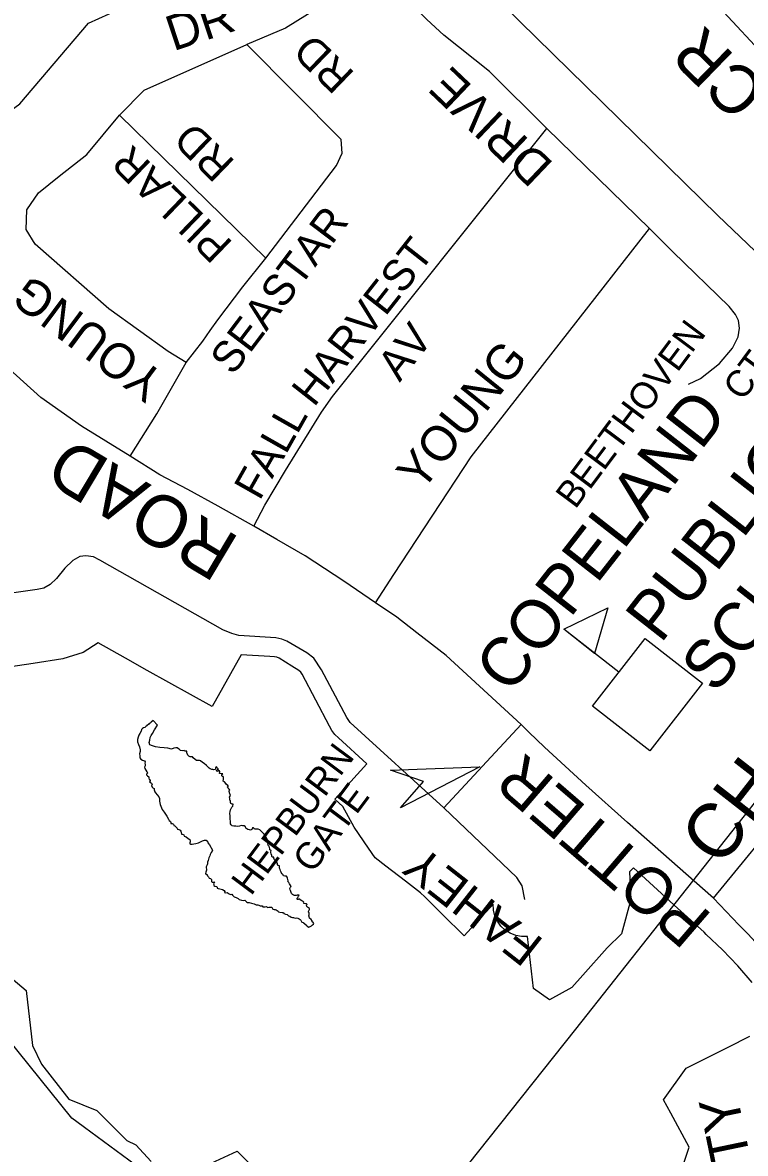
# Model space of a CAD drawing. Extents: x 586326 to 623965, y 4819854 to 4857850.
# Drawn here: x 599494 to 599867, y 4833487 to 4834070 of the extents above; entities that cross this region are included whole.
import ezdxf

# ---------------------------------------------------------------- set-up
doc = ezdxf.new("R2010")
doc.units = 0
for name, color, linetype in [('Hydro ROW', 7, 'Continuous'), ('Lots_Concessions', 7, 'Continuous'), ('Major Rds and Hwys', 7, 'Continuous'), ('Major Rds Lbls', 7, 'Continuous'), ('Minor Rd Lbls', 7, 'Continuous'), ('Minor Rds', 7, 'Continuous'), ('Park Outlines', 7, 'Continuous'), ('Proposed Secondary Rds', 7, 'Continuous'), ('School Syms_Lbls', 7, 'Continuous'), ('Secondary Rds Lbls', 7, 'Continuous'), ('SWM Ponds', 7, 'Continuous')]:
    doc.layers.add(name, color=color, linetype=linetype)

msp = doc.modelspace()

# ---------------------------------------------------------------- linework, layer by layer
at = {"layer": 'Hydro ROW'}
for p, q in [((599519.76, 4833504.76), (599376.71, 4833681.65)), ((599616.47, 4833433.79), (599519.76, 4833504.76))]:
    msp.add_line(p, q, dxfattribs=at)
at = {"layer": 'Lots_Concessions'}
for p, q in [((599779.82, 4833550.59), (599907.03, 4833711.59)), ((599701.81, 4833452.63), (599779.82, 4833550.59))]:
    msp.add_line(p, q, dxfattribs=at)
at = {"layer": 'Major Rds and Hwys'}
for points in [[(599853.16, 4833970.31), (599640.11, 4834179.09), (599625.32, 4834193.52)], [(600011.04, 4833819.79), (599853.16, 4833970.31)], [(599549.78, 4833846.2), (599524.65, 4833861.65), (599503.75, 4833876.57), (599485.78, 4833892.65), (599456.57, 4833921.05), (599440.34, 4833938.09)], [(599613.73, 4833810.19), (599595.23, 4833820.45), (599579.57, 4833828.97), (599565.15, 4833836.63), (599549.78, 4833846.2)], [(599676.54, 4833770.64), (599660.16, 4833781.82), (599640.14, 4833794.89), (599625.54, 4833803.28), (599613.73, 4833810.19)], [(599751.61, 4833707.8), (599712.93, 4833743.44), (599697.9, 4833755.12), (599687.5, 4833763.24), (599676.54, 4833770.64)], [(599850.89, 4833618.2), (599806.53, 4833657.23), (599785.04, 4833676.54), (599763.76, 4833696.09), (599755.61, 4833703.84), (599751.61, 4833707.8)], [(599917.3, 4833528.69), (599905.45, 4833552.08), (599897.62, 4833564.59), (599889.01, 4833577.45), (599882.52, 4833585.19), (599874.61, 4833593.5), (599868.63, 4833599.75), (599864.04, 4833604.44), (599850.89, 4833618.2)]]:
    msp.add_lwpolyline(points, dxfattribs=at)
at = {"layer": 'Minor Rd Lbls'}
for p, q in [((599684.25, 4833684.24), (599730.32, 4833685.92)), ((599730.32, 4833685.92), (599689.3, 4833664.89)), ((599701.29, 4833678.35), (599684.25, 4833684.24)), ((599689.3, 4833664.89), (599701.29, 4833678.35)), ((599701.29, 4833678.35), (599701.29, 4833678.35))]:
    msp.add_line(p, q, dxfattribs=at)
msp.add_lwpolyline([(599701.29, 4833678.35), (599684.25, 4833684.24), (599730.32, 4833685.92), (599689.3, 4833664.89)], close=True, dxfattribs=at)
at = {"layer": 'Minor Rds'}
for points in [[(600063.7, 4833991.31), (600016.02, 4833933.5), (600008.18, 4833930.72), (600001.43, 4833931.74), (599872.33, 4834058.03), (599779.99, 4834157.32), (599774.65, 4834167.73), (599778.38, 4834177.34), (599819.22, 4834217.1), (599838.97, 4834225.91), (599849.01, 4834228.09), (599876.87, 4834228.31)], [(599764.98, 4834015.28), (599735.33, 4834044.61), (599711.8, 4834063.4), (599702.97, 4834071.54), (599683.31, 4834091.25), (599674.93, 4834093.98), (599667.98, 4834093.53), (599646.42, 4834077.06), (599629.95, 4834066.99), (599610.04, 4834058.64)], [(599544.4, 4834022.09), (599557.14, 4834034.97), (599610.04, 4834058.64)], [(599619.86, 4833948.34), (599656.42, 4833996.18), (599659.33, 4834002.54), (599658.69, 4834009.61), (599610.04, 4834058.64)], [(599578.8, 4833894.53), (599569.4, 4833900.18), (599538.79, 4833922.18), (599500.88, 4833955.62), (599496.21, 4833963.1), (599496.56, 4833973.34), (599502.46, 4833982.11), (599513.12, 4833990.72), (599527.41, 4834001.81), (599544.4, 4834022.09)], [(599619.86, 4833948.34), (599544.4, 4834022.09)], [(599613.73, 4833810.19), (599619.37, 4833820.99), (599629.97, 4833838.79), (599648.63, 4833868.98), (599654.33, 4833877.06), (599764.98, 4834015.28)], [(599817.9, 4833963.67), (599764.98, 4834015.28)], [(599676.54, 4833770.64), (599686.01, 4833785.17), (599725.78, 4833845.86), (599817.9, 4833963.67)], [(599829.99, 4833951.55), (599817.9, 4833963.67)], [(599578.8, 4833894.53), (599587.32, 4833905.63), (599591.16, 4833911.08), (599595.08, 4833916.47), (599607.95, 4833933.53), (599619.86, 4833948.34)], [(599838.1, 4833883.32), (599844.23, 4833886.24), (599854.12, 4833893.95), (599860.77, 4833901.9), (599863.69, 4833907.77), (599864.43, 4833912.2), (599863.88, 4833916.21), (599862.31, 4833919.37), (599859.05, 4833923.5), (599829.99, 4833951.55)], [(599549.78, 4833846.2), (599563.53, 4833868.02), (599578.8, 4833894.53)], [(599523.92, 4833794.47), (599520.29, 4833792.38), (599516.2, 4833788.49), (599511.83, 4833783.18), (599508.61, 4833780.11), (599505.27, 4833778.07), (599501.76, 4833777.45), (599467.93, 4833772.56), (599463.77, 4833772.13), (599460.81, 4833772.35), (599458.15, 4833773.27), (599455.38, 4833775.08), (599446.32, 4833789.37), (599427.36, 4833816.37)], [(599711.79, 4833664.86), (599663.43, 4833708.92), (599661.61, 4833711.5), (599648.58, 4833736.04), (599644.62, 4833741.99), (599641.07, 4833744.78), (599630.74, 4833750.86), (599628.19, 4833751.91), (599625.1, 4833752.47), (599605.9, 4833753.75), (599602.33, 4833754.68), (599597.76, 4833756.63), (599534.17, 4833792.59), (599530.83, 4833794.26), (599526.97, 4833794.84), (599523.92, 4833794.47)], [(599711.79, 4833664.86), (599751.61, 4833707.8)], [(599753.56, 4833617.57), (599752.17, 4833624.59), (599749.43, 4833628.82), (599711.79, 4833664.86)]]:
    msp.add_lwpolyline(points, dxfattribs=at)
at = {"layer": 'Park Outlines'}
msp.add_lwpolyline([(599623.52, 4834168.61), (599454.66, 4834061.42), (599443.22, 4834053.82), (599432.11, 4834045.77), (599421.33, 4834037.28), (599410.9, 4834028.36), (599400.84, 4834019.02), (599400.84, 4834019.02), (599401.01, 4834018.77), (599418.91, 4833993.11), (599422.94, 4833987.34), (599424.92, 4833989.2), (599456.28, 4834001.33), (599492.83, 4834027.93), (599528.31, 4834069.63), (599597.74, 4834100.97), (599616.92, 4834107.86), (599629.18, 4834119.39), (599654.99, 4834137.73), (599623.52, 4834168.61)], close=True, dxfattribs=at)
for points in [[(599870.95, 4833574.72), (599863.43, 4833583.37), (599855.52, 4833591.65), (599847.23, 4833599.57), (599846.05, 4833600.64), (599830.73, 4833614.61), (599830.5, 4833614.81), (599824.15, 4833620.63), (599809.59, 4833633.96), (599807.57, 4833631.75), (599808.33, 4833617.53), (599803.43, 4833599.89), (599796.1, 4833592.55), (599783.43, 4833578.46), (599777.82, 4833572.22), (599766.37, 4833565.79), (599757.97, 4833571.68), (599754.93, 4833598.51), (599751.88, 4833598.47), (599748.87, 4833599.02), (599746.02, 4833600.13), (599743.44, 4833601.76), (599741.21, 4833603.85), (599739.42, 4833606.33), (599738.14, 4833609.1), (599737.4, 4833612.06), (599737.24, 4833615.12), (599722.27, 4833598.76), (599711.01, 4833609.86), (599701.89, 4833618.84), (599699.78, 4833620.91), (599691.95, 4833626.94), (599681.77, 4833634.78), (599676.24, 4833639.03), (599672.84, 4833643.99), (599665.41, 4833654.81), (599659.56, 4833665.57), (599655.42, 4833669.35), (599671.99, 4833687.44), (599657.33, 4833700.87), (599655.55, 4833702.69), (599654, 4833704.71), (599652.69, 4833706.89), (599638.63, 4833733.77), (599637.86, 4833734.85), (599636.83, 4833735.7), (599633.34, 4833737.86), (599626.71, 4833741.97), (599625.59, 4833742.49), (599624.39, 4833742.71), (599621.89, 4833742.87), (599607.13, 4833743.81), (599592.23, 4833717.07), (599581.05, 4833723.3), (599569.87, 4833729.52), (599558.69, 4833735.75), (599547.51, 4833741.97), (599533.26, 4833749.91), (599525.6, 4833744.97), (599515.09, 4833741.62), (599499.72, 4833739.32), (599487.07, 4833737.43)], [(599445.1, 4833613.62), (599496.12, 4833570.54), (599499.42, 4833542.27), (599504.06, 4833532.65), (599518.22, 4833514.57), (599532.63, 4833508.78), (599548.05, 4833493.23), (599552.7, 4833491.03), (599560.63, 4833482.42)], [(599870.9, 4833380.77), (599856.78, 4833389.8), (599856.08, 4833400.25), (599855.59, 4833407.74), (599840.99, 4833411.77), (599832.79, 4833414.03), (599833.59, 4833422.5), (599834.81, 4833435.37), (599835.43, 4833441.8), (599831.69, 4833447.16), (599826.41, 4833454.72), (599827.78, 4833458.73), (599832.48, 4833472.47), (599837.17, 4833486.2), (599838.38, 4833489.74), (599828.87, 4833507.35), (599825.19, 4833514.16), (599836.81, 4833530.57), (599858.46, 4833541.35), (599869.74, 4833546.97)], [(599584.86, 4833478.44), (599605.14, 4833487.74), (599630.57, 4833461.99)]]:
    msp.add_lwpolyline(points, dxfattribs=at)
at = {"layer": 'Proposed Secondary Rds'}
msp.add_lwpolyline([(599850.89, 4833618.2), (599890.96, 4833667.06), (599934.82, 4833723.2), (599981.58, 4833783.54), (600011.04, 4833819.79)], dxfattribs=at)
at = {"layer": 'School Syms_Lbls'}
msp.add_line((599802.04, 4833734.77), (599773.63, 4833756.96), dxfattribs=at)
for points in [[(599773.63, 4833756.96), (599796.41, 4833768), (599789.5, 4833744.49)], [(599788.41, 4833717.32), (599815.67, 4833752.22), (599845.28, 4833729.09), (599818.01, 4833694.19)]]:
    msp.add_lwpolyline(points, close=True, dxfattribs=at)
at = {"layer": 'SWM Ponds'}
msp.add_lwpolyline([(599554.2, 4833697.53), (599554.7, 4833696.26), (599554.98, 4833694.71), (599554.94, 4833693.81), (599554.74, 4833692.64), (599554.85, 4833691.73), (599554.88, 4833690.58), (599555.34, 4833689.92), (599556.23, 4833689.42), (599556.72, 4833689.19), (599557.25, 4833689.14), (599557.6, 4833688.61), (599557.42, 4833687.93), (599557.52, 4833687.13), (599557.51, 4833686.52), (599557.26, 4833685.74), (599557.49, 4833685.05), (599557.9, 4833684.32), (599558.52, 4833683.42), (599558.89, 4833682.83), (599558.23, 4833682.26), (599558.2, 4833681.88), (599558.83, 4833681.39), (599559.48, 4833680.83), (599559.53, 4833680.17), (599559.67, 4833679.5), (599560.25, 4833679.2), (599560.11, 4833678.75), (599559.85, 4833678.23), (599560.88, 4833677.58), (599561.13, 4833676.77), (599560.87, 4833676.31), (599561.22, 4833675.51), (599561.61, 4833675.16), (599562.16, 4833674.74), (599562.27, 4833674.03), (599562.54, 4833673), (599562.91, 4833672.55), (599563.78, 4833671.57), (599564.58, 4833670.48), (599565.01, 4833669.58), (599564.91, 4833668.22), (599565.26, 4833666.56), (599566.33, 4833663.98), (599567.33, 4833662.64), (599568.82, 4833660.55), (599569.59, 4833658.97), (599569.96, 4833658.32), (599570.62, 4833657.86), (599570.9, 4833657.23), (599570.87, 4833656.79), (599571.49, 4833656.67), (599572.16, 4833656.35), (599572.33, 4833655.7), (599572.93, 4833655.49), (599573.5, 4833655.04), (599574.04, 4833654.42), (599574.34, 4833653.82), (599575.03, 4833653.65), (599575.73, 4833653.3), (599575.97, 4833652.75), (599576.2, 4833651.86), (599576.27, 4833651.29), (599576.9, 4833651.31), (599577.6, 4833650.97), (599577.75, 4833650.29), (599578.79, 4833649.79), (599579.74, 4833649.04), (599580.71, 4833648.44), (599580.87, 4833647.83), (599580.76, 4833647.25), (599580.68, 4833646.82), (599580.71, 4833646.33), (599581.06, 4833646.06), (599581.78, 4833646.06), (599582.79, 4833646.3), (599583.78, 4833646.45), (599585.05, 4833646.84), (599586.1, 4833647.26), (599587.13, 4833647.79), (599588.15, 4833648.17), (599589.1, 4833648.14), (599589.8, 4833647.59), (599589.98, 4833646.84), (599590.74, 4833645.78), (599592.42, 4833642.93), (599592.22, 4833642.42), (599591.66, 4833641.83), (599591.07, 4833640.81), (599590.99, 4833640.05), (599590.51, 4833638.98), (599590.15, 4833637.73), (599589.84, 4833636.74), (599589.78, 4833636.01), (599589.59, 4833635.5), (599589.13, 4833634.32), (599589.23, 4833632.75), (599588.87, 4833631.69), (599588.79, 4833630.99), (599589.05, 4833630.48), (599589.61, 4833630.4), (599589.84, 4833629.71), (599590.28, 4833629.16), (599590.68, 4833628.49), (599591.31, 4833628.31), (599591.79, 4833627.9), (599591.83, 4833627.28), (599591.87, 4833626.79), (599592.13, 4833626.48), (599592.71, 4833626.49), (599593.45, 4833626.58), (599593.07, 4833626.1), (599592.93, 4833625.65), (599592.98, 4833625.2), (599593.05, 4833624.69), (599593.63, 4833624.39), (599594.45, 4833624.31), (599594.7, 4833623.91), (599594.82, 4833623.41), (599595.32, 4833623.27), (599596.17, 4833622.97), (599596.9, 4833622.86), (599597.56, 4833622.65), (599598.34, 4833622.2), (599598.77, 4833621.7), (599598.59, 4833621.08), (599599.15, 4833620.94), (599599.91, 4833621.07), (599600.99, 4833620.48), (599601.61, 4833620.15), (599602.28, 4833620.32), (599602.74, 4833619.82), (599603.48, 4833619), (599604.52, 4833618.49), (599605.65, 4833618.1), (599606.19, 4833617.6), (599607.35, 4833617.26), (599608.15, 4833617.09), (599608.95, 4833617.14), (599609.85, 4833616.38), (599610.39, 4833615.96), (599611.28, 4833615.98), (599612.43, 4833615.6), (599613.77, 4833615.22), (599614.91, 4833614.84), (599615.74, 4833614.86), (599616.33, 4833614.55), (599617.02, 4833614.32), (599617.59, 4833614.34), (599618.05, 4833614.33), (599618.36, 4833613.74), (599618.83, 4833613.68), (599619.48, 4833613.73), (599620.24, 4833613.85), (599620.78, 4833613.49), (599621.38, 4833613.53), (599622.04, 4833613.53), (599622.92, 4833613.58), (599623.16, 4833613.17), (599623.51, 4833612.59), (599624.22, 4833612.44), (599624.68, 4833612.44), (599625.26, 4833612.19), (599625.65, 4833611.84), (599626.23, 4833611.54), (599626.45, 4833611.22), (599627.15, 4833611.07), (599628.33, 4833610.87), (599628.91, 4833610.77), (599629.21, 4833610.29), (599630.03, 4833609.9), (599630.93, 4833609.8), (599631.6, 4833609.14), (599632.29, 4833608.92), (599632.87, 4833608.4), (599633.63, 4833608.27), (599634.15, 4833608.27), (599634.95, 4833607.85), (599635.65, 4833608.03), (599636.33, 4833607.91), (599637.15, 4833607.58), (599637.64, 4833607.29), (599637.99, 4833606.82), (599638.32, 4833606.25), (599638.51, 4833605.9), (599639.37, 4833605.75), (599639.37, 4833605.43), (599640, 4833604.99), (599641.03, 4833604.18), (599641.18, 4833603.86), (599642.05, 4833603.34), (599642.35, 4833603.46), (599642.76, 4833603.66), (599643.08, 4833603.87), (599643.4, 4833604.02), (599643.96, 4833604.41), (599644.46, 4833604.79), (599644.66, 4833605.24), (599644.37, 4833605.73), (599643.82, 4833606.06), (599643.72, 4833606.6), (599643.24, 4833607.23), (599642.4, 4833607.93), (599642.16, 4833608.54), (599642.06, 4833609.07), (599642.19, 4833609.69), (599642.19, 4833610.62), (599641.86, 4833610.92), (599641.85, 4833611.29), (599642.11, 4833611.76), (599642.39, 4833612.31), (599642.42, 4833612.95), (599641.93, 4833613.18), (599641.39, 4833613.6), (599641.03, 4833613.99), (599640.84, 4833614.6), (599641.13, 4833615.04), (599640.83, 4833615.37), (599640.28, 4833615.39), (599639.67, 4833615.46), (599639.31, 4833615.99), (599639.45, 4833616.24), (599639.13, 4833616.55), (599638.51, 4833616.88), (599637.56, 4833617.36), (599636.95, 4833617.89), (599636.63, 4833617.62), (599636.21, 4833617.54), (599635.84, 4833617.83), (599635.98, 4833618.24), (599636.44, 4833618.54), (599636.74, 4833619.22), (599637, 4833619.8), (599636.62, 4833619.84), (599636.09, 4833619.69), (599635.48, 4833619.56), (599634.73, 4833619.52), (599634.19, 4833619.69), (599633.56, 4833620.13), (599633.19, 4833620.57), (599633.03, 4833621.16), (599632.74, 4833621.64), (599632.54, 4833622.11), (599632.42, 4833622.61), (599632.34, 4833623.29), (599632.53, 4833623.86), (599632.93, 4833624.31), (599632.44, 4833625.06), (599632.13, 4833625.66), (599631.68, 4833626.32), (599631.18, 4833626.86), (599631.4, 4833627.21), (599631.29, 4833627.8), (599631.1, 4833628.47), (599630.93, 4833629.11), (599630.5, 4833629.6), (599629.63, 4833629.61), (599629.07, 4833629.69), (599628.87, 4833630.21), (599628.5, 4833630.6), (599628.09, 4833630.86), (599627.71, 4833631.68), (599627.42, 4833632.37), (599627.26, 4833633.01), (599626.99, 4833633.73), (599626.85, 4833634.46), (599626.93, 4833634.96), (599626.19, 4833635.12), (599625.96, 4833635.56), (599625.94, 4833636.19), (599625.6, 4833636.61), (599625.41, 4833637.22), (599624.83, 4833637.52), (599624.33, 4833638.06), (599624.04, 4833638.81), (599624.08, 4833639.39), (599623.25, 4833639.37), (599623.04, 4833639.69), (599622.91, 4833640.25), (599622.66, 4833641.11), (599622.49, 4833641.81), (599622.39, 4833642.15), (599622.61, 4833642.9), (599622, 4833643.22), (599621.9, 4833643.76), (599621.82, 4833644.44), (599621.67, 4833644.97), (599621.32, 4833645.19), (599621.1, 4833645.62), (599620.93, 4833646.26), (599621.34, 4833646.66), (599621.09, 4833647.12), (599620.78, 4833647.58), (599620.84, 4833647.92), (599620.54, 4833648.72), (599620.21, 4833649.34), (599619.76, 4833650.15), (599618.94, 4833651.2), (599618.3, 4833651.96), (599617.64, 4833652.68), (599616.83, 4833653.42), (599615.97, 4833653.83), (599615.3, 4833653.89), (599614.35, 4833653.86), (599613.86, 4833653.95), (599613.87, 4833654.24), (599613.44, 4833654.47), (599613.04, 4833654.48), (599612.75, 4833654.04), (599612.59, 4833653.65), (599611.94, 4833653.34), (599611.37, 4833653.53), (599610.63, 4833653.7), (599610.03, 4833653.91), (599609.63, 4833654.32), (599609.35, 4833654.95), (599608.68, 4833655.47), (599607.75, 4833655.53), (599607.22, 4833655.64), (599606.29, 4833655.44), (599605.4, 4833655.21), (599604.43, 4833655.41), (599603.39, 4833655.4), (599602.45, 4833655.51), (599601.96, 4833656), (599601.66, 4833656.6), (599601.58, 4833657.48), (599601.4, 4833659.42), (599601.43, 4833660.78), (599601.33, 4833661.83), (599601.47, 4833662.85), (599601.68, 4833663.72), (599601.93, 4833664.44), (599602.34, 4833665.09), (599602.81, 4833665.76), (599603.01, 4833666.67), (599602.46, 4833666.75), (599601.75, 4833667.1), (599601.6, 4833667.62), (599601.68, 4833668.38), (599601.37, 4833668.83), (599601.21, 4833669.62), (599601.19, 4833670.25), (599601.61, 4833671.11), (599601.54, 4833671.62), (599601.23, 4833672.02), (599601.11, 4833672.58), (599600.98, 4833673.4), (599601.31, 4833674.01), (599600.94, 4833674.4), (599600.34, 4833675.07), (599600.16, 4833675.65), (599600.62, 4833675.83), (599600.29, 4833676.39), (599599.59, 4833676.94), (599599.16, 4833677.44), (599598.49, 4833678.16), (599597.86, 4833678.63), (599597.99, 4833679.61), (599598.1, 4833680.42), (599597.89, 4833681), (599597.52, 4833680.92), (599597.21, 4833681.27), (599597.21, 4833681.83), (599597.63, 4833682.38), (599596.76, 4833682.44), (599595.89, 4833682.45), (599596.1, 4833683.37), (599596.03, 4833683.88), (599595.64, 4833683.83), (599595, 4833683.61), (599594.57, 4833683.72), (599594.4, 4833684.28), (599594.86, 4833684.54), (599595.41, 4833684.68), (599595.35, 4833684.98), (599594.76, 4833685.54), (599594.33, 4833686.03), (599594.1, 4833685.8), (599593.93, 4833685.26), (599593.75, 4833684.64), (599593.08, 4833684.44), (599592.55, 4833684.6), (599591.99, 4833684.68), (599591.06, 4833685), (599590.59, 4833685.31), (599590.15, 4833685.81), (599589.21, 4833686.64), (599588.07, 4833687.74), (599587.25, 4833688.27), (599586.23, 4833689.13), (599585.69, 4833689.29), (599585.2, 4833689.26), (599584.52, 4833689.18), (599584.02, 4833689.32), (599583.41, 4833689.79), (599582.42, 4833690.56), (599581.99, 4833691.06), (599581.44, 4833691.08), (599580.8, 4833691.11), (599580.09, 4833691.46), (599579.57, 4833691.99), (599579.26, 4833692.88), (599579.01, 4833693.28), (599579.09, 4833693.98), (599578.65, 4833694.07), (599577.9, 4833694), (599577.65, 4833694.44), (599576.66, 4833694.29), (599575.76, 4833694.34), (599575.27, 4833694.87), (599574.84, 4833695.31), (599574.03, 4833695.78), (599573.43, 4833695.74), (599572.36, 4833695.55), (599571.14, 4833695.17), (599569.35, 4833695.64), (599567.45, 4833695.69), (599565.23, 4833695.88), (599562.93, 4833696.35), (599561.85, 4833696.68), (599560.9, 4833696.91), (599559.92, 4833697.36), (599559.73, 4833698.44), (599559.92, 4833699.73), (599560.21, 4833701.14), (599560.71, 4833702.19), (599561.33, 4833703.24), (599562.44, 4833705.05), (599563.88, 4833707.41), (599561.79, 4833709.86), (599560.62, 4833709.03), (599560.14, 4833708.54), (599559.6, 4833708.24), (599559.22, 4833707.82), (599558.85, 4833707.49), (599558.48, 4833707.55), (599558.42, 4833707.06), (599558, 4833706.72), (599557.47, 4833706.31), (599556.8, 4833706.17), (599556.13, 4833705.77), (599555.65, 4833705.16), (599555.44, 4833704.3), (599554.91, 4833703.23), (599554.3, 4833702.38), (599553.94, 4833701.27), (599553.65, 4833700.11), (599553.65, 4833698.93)], close=True, dxfattribs=at)

# ---------------------------------------------------------------- texts
at = {"layer": 'Major Rds Lbls'}
for s, height, rotation, p in [('ROAD', 26.76, 149.17137, (599607.15, 4833803.78)), ('POTTER', 23.959, 139.27751, (599851, 4833609.19))]:
    msp.add_text(s, height=height, rotation=rotation, dxfattribs=at).set_placement(p)
at = {"layer": 'Minor Rd Lbls'}
for s, height, rotation, p in [('DR ', 18.086, 18.31159, (599572.11, 4834055.03)), ('CUTTERS CR', 25.002, 135.85622, (599999.82, 4833919.28)), ('RD', 16.031, 135.97944, (599666.27, 4834043.62)), ('DRIVE', 18.086, 136.40833, (599768.97, 4833997.02)), ('RD', 16.031, 135.97944, (599604.56, 4833998.06)), ('PILLAR', 16.031, 135.97944, (599603.41, 4833956.22)), ('SEASTAR', 16.031, 52.85837, (599602.84, 4833887.38)), ('HARVEST', 16.031, 51.84284, (599644.73, 4833871.09)), ('YOUNG ', 18.086, 143.20262, (599569.1, 4833887.4)), ('AV', 16.031, 51.84284, (599688.97, 4833884.03)), ('BEETHOVEN', 13.788, 53.23564, (599779.58, 4833818.45)), ('YOUNG ', 18.086, 51.06417, (599700.2, 4833827.38)), ('CT', 13.788, 53.23564, (599865.97, 4833874.09)), ('FALL', 16.031, 60.49047, (599616.68, 4833822.83)), ('HEPBURN', 13.788, 53.23564, (599612.19, 4833618.96)), ('GATE', 13.788, 53.23564, (599643.87, 4833630.46)), ('FAHEY  ', 18.086, 141.85497, (599763.98, 4833596.29)), ('SOLIDARITY', 20.356, 101.75182, (599896.06, 4833359.21))]:
    msp.add_text(s, height=height, rotation=rotation, dxfattribs=at).set_placement(p)
at = {"layer": 'School Syms_Lbls'}
for s, p in [('COPELAND', (599746.04, 4833722.79)), ('PUBLIC ', (599823.67, 4833749.08)), ('SCHOOL', (599852.25, 4833723.04))]:
    msp.add_text(s, height=25, rotation=52.00002, dxfattribs=at).set_placement(p)
at = {"layer": 'Secondary Rds Lbls'}
msp.add_text('CHAROLAIS', height=28.139, rotation=52.0507, dxfattribs=at).set_placement((599854.29, 4833633.31))

doc.saveas('drawing.dxf')
